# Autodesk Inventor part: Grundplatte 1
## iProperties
Created: 2004-11
Part Number: Grundplatte 1
Document SubType Name: Modeling
Designer: PALME
Manufacturer: Standard
Standards Organization: Custom
Author: PALME
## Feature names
1. Extrusion1
2. Extrusion2
